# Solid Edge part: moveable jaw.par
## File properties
Title: Moveable Jaw
Author: Deepak Maini
Template: Normal.par
Last saved by: Robert a Rhodes jr
Revision: 9
Application: Solid Edge
Material: iron
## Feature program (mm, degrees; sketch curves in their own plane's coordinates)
sketch for "unnamed Protrusion 1" plane through (0, 0, 0) normal (0, -1, 0) x-axis (1, 0, 0)
  line (-36.5256, 25.2528) -> (-36.5256, -34.7472)
  line (-36.5256, -34.7472) -> (-33.0256, -34.7472)
  line (-33.0256, -34.7472) -> (-33.0256, -32.2472)
  line (-33.0256, -32.2472) -> (-30.5256, -32.2472)
  line (-30.5256, -32.2472) -> (-30.5256, -29.7472)
  line (-30.5256, -29.7472) -> (-28.0256, -29.7472)
  line (-28.0256, -29.7472) -> (-28.0256, -27.2472)
  line (-28.0256, -27.2472) -> (-25.5256, -27.2472)
  line (-25.5256, -27.2472) -> (-25.5256, -24.7472)
  line (-25.5256, -24.7472) -> (-23.0256, -24.7472)
  line (-23.0256, -24.7472) -> (-23.0256, -22.2472)
  line (-23.0256, -22.2472) -> (-20.5256, -22.2472)
  line (-20.5256, -22.2472) -> (-20.5256, -19.7472)
  line (-20.5256, -19.7472) -> (-18.0256, -19.7472)
  line (-18.0256, -22.2472) -> (-18.0256, -19.7472)
  line (-15.5256, -22.2472) -> (-18.0256, -22.2472)
  line (-15.5256, -24.7472) -> (-15.5256, -22.2472)
  line (-13.0256, -24.7472) -> (-15.5256, -24.7472)
  line (-13.0256, -27.2472) -> (-13.0256, -24.7472)
  line (-10.5256, -27.2472) -> (-13.0256, -27.2472)
  line (-10.5256, -29.7472) -> (-10.5256, -27.2472)
  line (-8.0256, -29.7472) -> (-10.5256, -29.7472)
  line (-8.0256, -32.2472) -> (-8.0256, -29.7472)
  line (-5.5256, -32.2472) -> (-8.0256, -32.2472)
  line (-5.5256, -34.7472) -> (-5.5256, -32.2472)
  line (-2.0256, -34.7472) -> (-5.5256, -34.7472)
  line (-2.0256, -34.7472) -> (-2.0256, 25.2528)
  line (-2.0256, 25.2528) -> (-36.5256, 25.2528)
extrude "unnamed Protrusion 1" add finite 18 along -normal
sketch for "unnamed Hole 1" plane through (-19.2756, 9, 25.2528) normal (0, 0, 1) x-axis (1, 0, 0)
  hole centre (0, 0) bore radius 6
hole "unnamed Hole 1" finite
sketch for "unnamed Hole 2" plane through (-2.0256, 9, -4.7472) normal (1, 0, 0) x-axis (0, 1, 0)
  hole centre (0, 23) bore radius 4.5
hole "unnamed Hole 2" through
chamfer "unnamed Chamfer 1"
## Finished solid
Body 1: solid body, 38 faces, 98 edges, 60 vertices.
  Faces by surface: plane 34, cylinder 3, cone 1
  Edges by curve: line 92, circle 4, intersection 2
Bounding box of the edges (mm): 34.500 x 18.000 x 60.000, from (-36.5256, 0, -34.7472) to (-2.0256, 18, 25.2528).
Cylindrical faces by radius (mm): R4.5 x2, R6 x1
Conical faces (half-angle, radius in mm at the cone's reference point): 59 deg R6 x1
Planar faces by outward normal: +x 7, +y 1, +z 1, -x 7, -y 1, -z 13, oblique 4
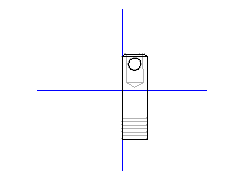
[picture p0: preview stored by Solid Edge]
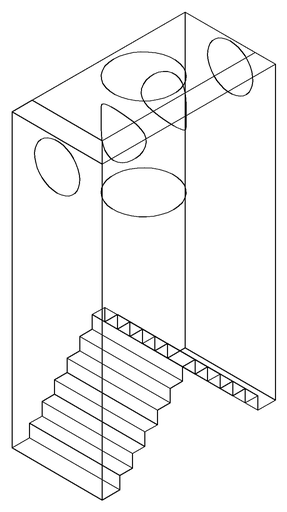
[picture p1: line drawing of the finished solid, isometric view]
